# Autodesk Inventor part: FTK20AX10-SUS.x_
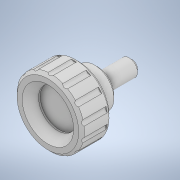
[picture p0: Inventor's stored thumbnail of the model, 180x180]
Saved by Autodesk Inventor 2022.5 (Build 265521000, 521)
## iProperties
Created: 2023-10
Part Number: FTK20AX10-SUS.x_
Material: 一般
Document SubType Name: Modeling
Designer: ImaoCorp
Density: 1 g/cm^3
Appearance: 既定
Sending System: SOLIDWORKS 2021-2021301
MC: AMD64
MC_MODEL: Intel64 Family 6 Model 60 Stepping 3, GenuineIntel
OS: Windows_NT
FRU: Parasolid Version 32.1, build 255,  1- 1-2021
FORMAT: text
GUISE: transmit
KEY: FTK20AX10-SUS
FILE: FTK20AX10-SUS.x_t
DATE: Tue Oct 17 11:07:15 2023
Author: ImaoCorp
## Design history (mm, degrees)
feature "Base1"
node "ソリッド1"
